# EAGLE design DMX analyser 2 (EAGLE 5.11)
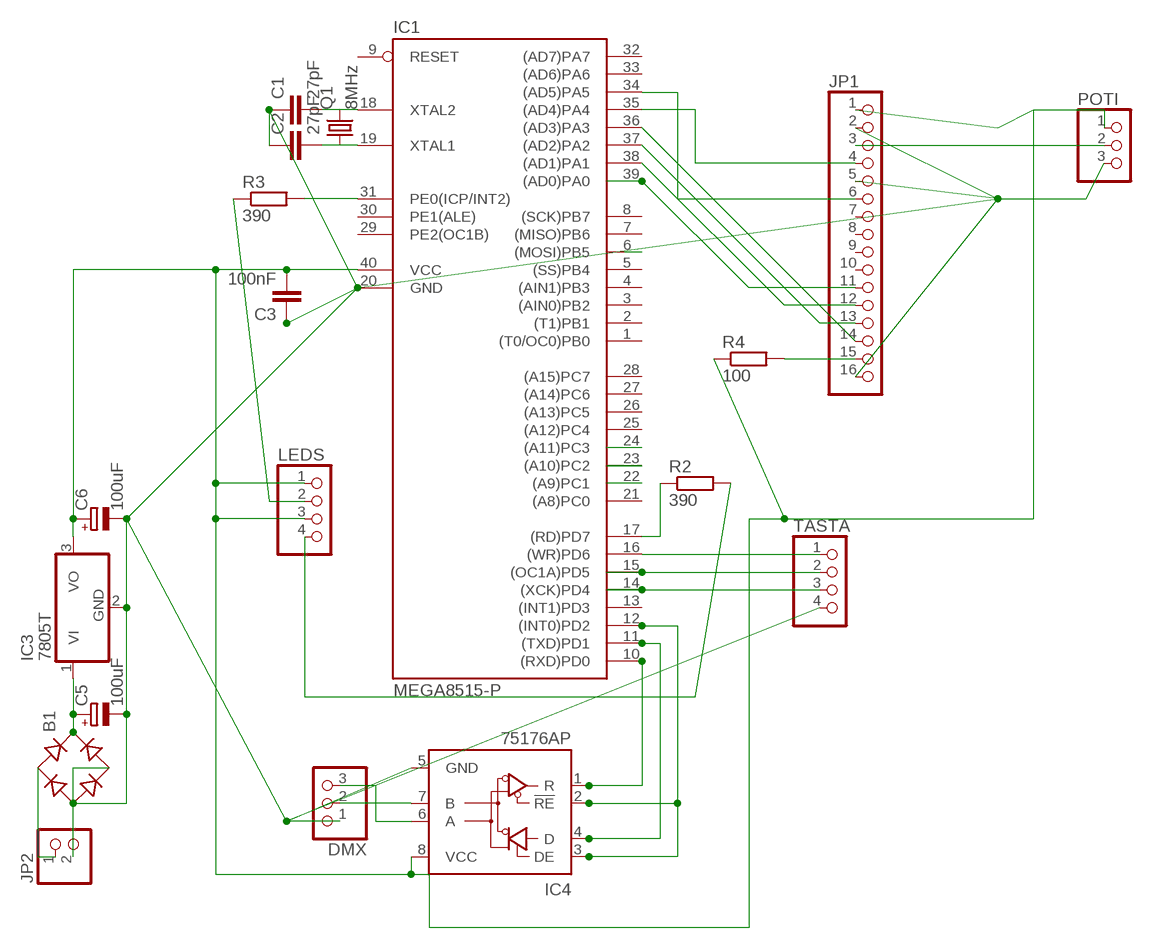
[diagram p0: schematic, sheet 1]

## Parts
B1  RB1A  [RB1A]
C1  27pF  C2,5-3  [C2.5-3]
C2  27pF  C2,5-3  [C2.5-3]
C3  100nF  C2.5/5  [C2.5-5]
C5  100uF  CPOL-EUE2.5-6  [E2,5-6]
C6  100uF  CPOL-EUE2.5-6  [E2,5-6]
DMX  PINHD-1X3/90  [1X03/90]
IC1  MEGA8515-P  [DIL40]
IC3  7805T  [TO220H]
IC4  75176AP  [DIL08]
JP1  PINHD-1X16  [1X16]
JP2  PINHD-1X2/90  [1X02/90]
LEDS  PINHD-1X4/90  [1X04/90]
POTI  PINHD-1X3/90  [1X03/90]
Q1  8MHz  CRYSTALHC49S  [HC49/S]
R2  390  R-EU_M1206  [M1206]
R3  390  R-EU_M1206  [M1206]
R4  100  R-EU_M1206  [M1206]
TASTA  PINHD-1X4/90  [1X04/90]

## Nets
N$1: C1.2 IC1.18(XTAL2) Q1.2
N$2: C2.2 IC1.19(XTAL1) Q1.1
N$3: DMX.2 IC4.7(B)
N$4: DMX.3 IC4.6(A)
N$5: IC1.6((MOSI)PB5)
N$6: JP1.3 POTI.2
N$7: IC1.10((RXD)PD0) IC4.1(R)
N$8: IC1.11((TXD)PD1) IC4.4(D)
N$9: IC1.16((WR)PD6) TASTA.1
N$10: C3.2 C6.+ IC1.40(VCC) IC3.3(VO) IC4.8(VCC) JP1.1 LEDS.1 LEDS.3 POTI.1 R4.1
N$11: LEDS.2 R3.1
N$12: LEDS.4 R2.2
N$13: IC1.31(PE0(ICP/INT2)) R3.2
N$14: IC1.35((AD4)PA4) JP1.4
N$15: B1.AC1 JP2.1
N$16: B1.+ C5.+ IC3.1(VI)
N$17: IC1.12((INT0)PD2) IC4.2(!RE) IC4.3(DE)
N$18: IC1.34((AD5)PA5) JP1.6
N$21: IC1.36((AD3)PA3) JP1.14
N$23: IC1.17((RD)PD7) R2.1
N$24: IC1.37((AD2)PA2) JP1.13
N$25: IC1.38((AD1)PA1) JP1.12
N$26: JP1.15 R4.2
N$27: B1.AC2 JP2.2
N$28: IC1.24((A11)PC3)
N$29: IC1.23((A10)PC2)
N$30: IC1.22((A9)PC1)
N$31: B1.- C1.1 C2.1 C3.1 C5.- C6.- DMX.1 IC1.20(GND) IC3.2(GND) IC4.5(GND) JP1.2 JP1.5 JP1.16 POTI.3 TASTA.4
N$37: IC1.39((AD0)PA0) JP1.11
N$64: IC1.15((OC1A)PD5) TASTA.2
N$65: IC1.14((XCK)PD4) TASTA.3
Unconnected: IC1.1((T0/OC0)PB0) IC1.2((T1)PB1) IC1.3((AIN0)PB2) IC1.4((AIN1)PB3) IC1.5((SS)PB4) IC1.7((MISO)PB6) IC1.8((SCK)PB7) IC1.9(RESET) IC1.13((INT1)PD3) IC1.21((A8)PC0) IC1.25((A12)PC4) IC1.26((A13)PC5) IC1.27((A14)PC6) IC1.28((A15)PC7) IC1.29(PE2(OC1B)) IC1.30(PE1(ALE)) IC1.32((AD7)PA7) IC1.33((AD6)PA6) JP1.7 JP1.8 JP1.9 JP1.10

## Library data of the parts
B1 = rectifier:RB1A: RECTIFIER 1 A
C1-C3 = capacitor-wima:C: CAPACITOR
C5 C6 = rcl:CPOL-EU: POLARIZED CAPACITOR, European symbol
DMX POTI = pinhead:PINHD-1X3: PIN HEADER
IC1 = atmel:MEGA8515-P: MICROCONTROLLER 8 Kbytes FLASH 512 bytes SRAM 512 bytes EEPROM USART 8-channel 10 bit ADC Source: avr.lbr; MPN: ATMEGA8515-16PU; OC_FARNELL: 9171401; OC_NEWARK: 01M6905
IC3 = linear:78*: Positive VOLTAGE REGULATOR Source: http://cache.national.com/ds/LM/LM78L05.pdf http://www.fairchildsemi.com/ds/LM/LM7805.pdf
IC4 = 751xx:75176A: DIFFERENTIAL BUS TRANSCEIVER Source: http://focus.ti.com/lit/ds/symlink/sn75176a.pdf
JP1 = pinhead:PINHD-1X16: PIN HEADER
JP2 = pinhead:PINHD-1X2: PIN HEADER
LEDS TASTA = pinhead:PINHD-1X4: PIN HEADER
Q1 = crystal:CRYSTAL: CRYSTAL; OC_FARNELL: 1667008; OC_NEWARK: unknown
R2-R4 = resistor:R-EU_: RESISTOR, European symbol

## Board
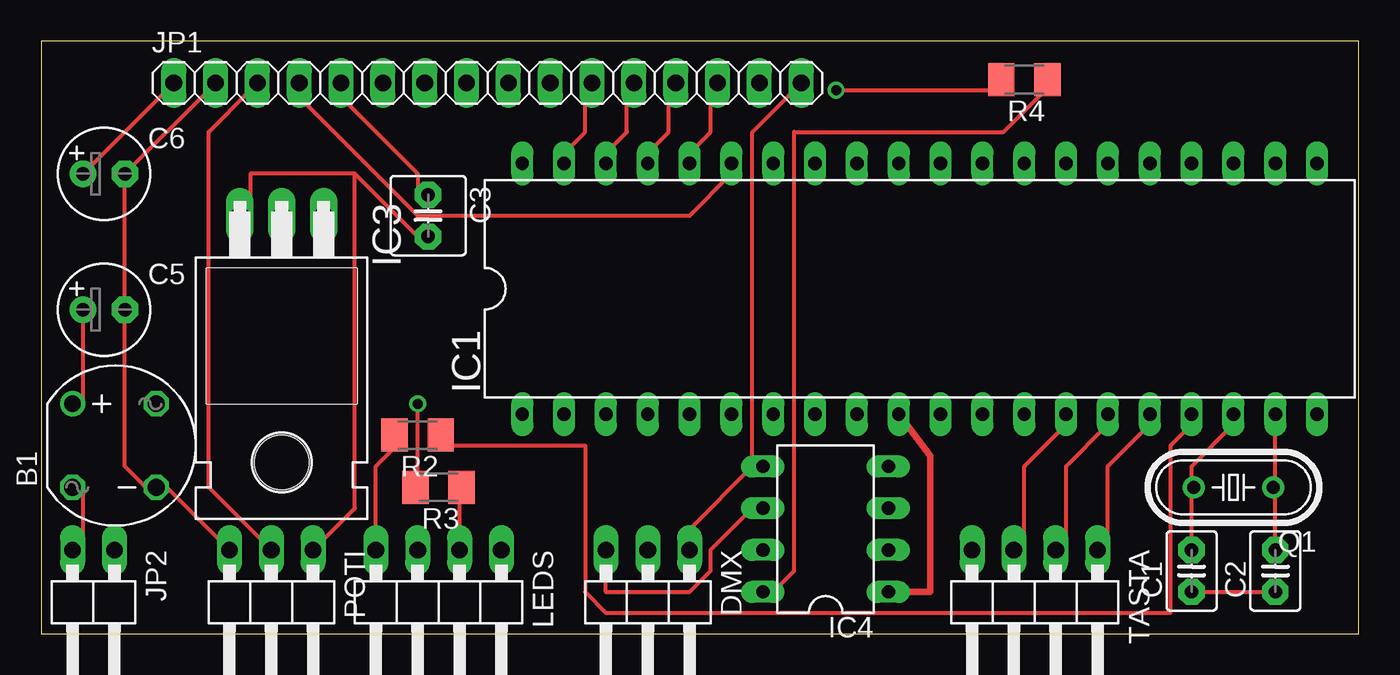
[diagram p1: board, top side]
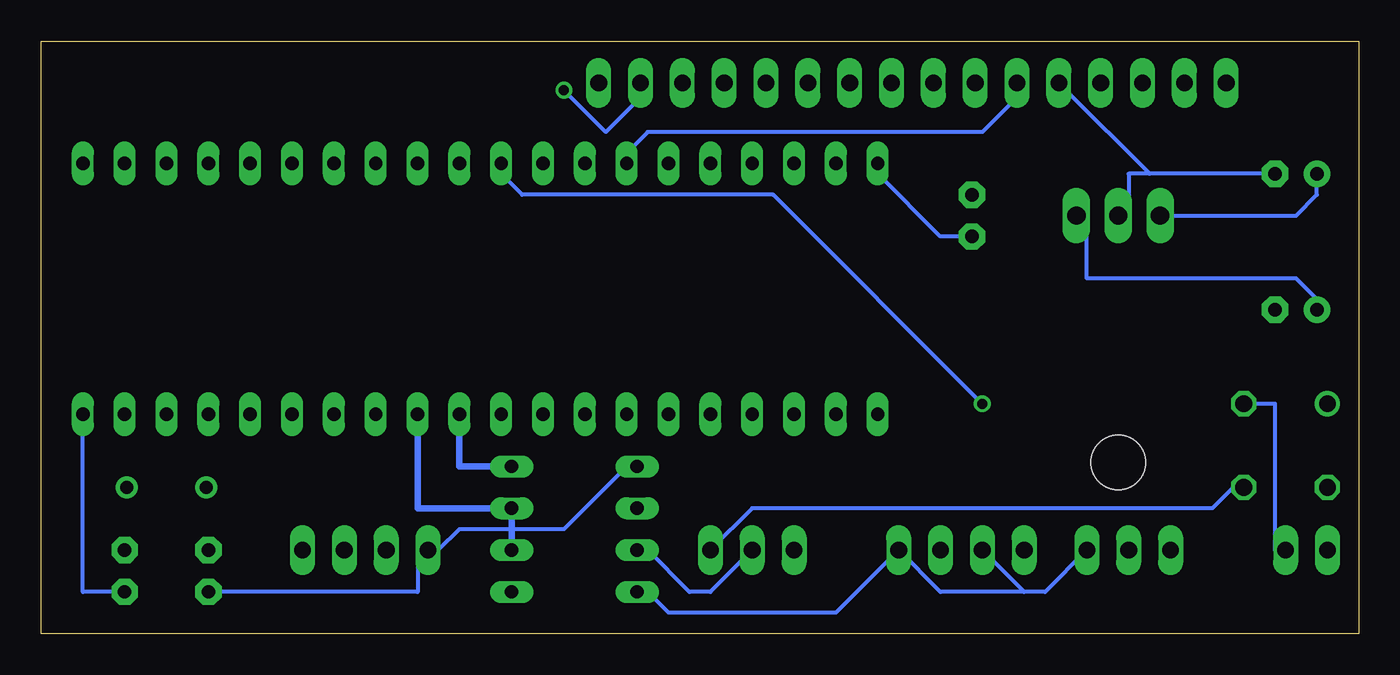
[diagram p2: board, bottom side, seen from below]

Size 80 x 36 mm. Coordinates in mm from the lower left corner, seen from the top.
Outline: 0,0 80,0 80,36 0,36 0,0
Copper layers (1*16): Top 0.035mm / dielectric 1.5mm / Bottom 0.035mm
Design rules "default": minimum track width 10mil, minimum drill 24mil, track to track 8mil, track to pad 8mil, pad to pad 8mil, via to via 8mil, smd to smd 8mil, copper to edge 40mil, drill to drill 8mil, minimum pad ring 10mil, minimum via ring 8mil, stop-mask expansion 4mil, vias tented up to drill 0mil, thermal gap 10mil

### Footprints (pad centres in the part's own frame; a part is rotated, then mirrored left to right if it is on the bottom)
RB1A = drill 1.016 round: + -2.54,2.54 | drill 1.016 octagon: - 2.54,-2.54; AC1 2.54,2.54; AC2 -2.54,-2.54
C2.5-3 = drill 0.813 pad 1.6 octagon: 1 -1.27,0; 2 1.27,0
C2.5-5 = drill 0.813 pad 1.6 octagon: 1 -1.27,0; 2 1.27,0
E2,5-6 = drill 0.813 pad 1.6 round: + -1.27,0 | drill 0.813 pad 1.6 octagon: - 1.27,0
1X03/90 = drill 1.016 long: 1 -2.54,-3.81; 2 0,-3.81; 3 2.54,-3.81
DIL40 = drill 0.813 long: 1 -24.13,-7.62; 2 -21.59,-7.62; 3 -19.05,-7.62; 4 -16.51,-7.62; 5 -13.97,-7.62; 6 -11.43,-7.62; 7 -8.89,-7.62; 8 -6.35,-7.62; 9 -3.81,-7.62; 10 -1.27,-7.62; 11 1.27,-7.62; 12 3.81,-7.62; 13 6.35,-7.62; 14 8.89,-7.62; 15 11.43,-7.62; 16 13.97,-7.62; 17 16.51,-7.62; 18 19.05,-7.62; 19 21.59,-7.62; 20 24.13,-7.62; 21 24.13,7.62; 22 21.59,7.62; 23 19.05,7.62; 24 16.51,7.62; 25 13.97,7.62; 26 11.43,7.62; 27 8.89,7.62; 28 6.35,7.62; 29 3.81,7.62; 30 1.27,7.62; 31 -1.27,7.62; 32 -3.81,7.62; 33 -6.35,7.62; 34 -8.89,7.62; 35 -11.43,7.62; 36 -13.97,7.62; 37 -16.51,7.62; 38 -19.05,7.62; 39 -21.59,7.62; 40 -24.13,7.62
TO220H = drill 1.118 long: 1 -2.54,-10.16; 2 0,-10.16; 3 2.54,-10.16 | hole 3.302: 0,4.826
DIL08 = drill 0.813 long: 1 -3.81,-3.81; 2 -1.27,-3.81; 3 1.27,-3.81; 4 3.81,-3.81; 5 3.81,3.81; 6 1.27,3.81; 7 -1.27,3.81; 8 -3.81,3.81
1X16 = drill 1.016 long: 1 -19.05,0; 2 -16.51,0; 3 -13.97,0; 4 -11.43,0; 5 -8.89,0; 6 -6.35,0; 7 -3.81,0; 8 -1.27,0; 9 1.27,0; 10 3.81,0; 11 6.35,0; 12 8.89,0; 13 11.43,0; 14 13.97,0; 15 16.51,0; 16 19.05,0
1X02/90 = drill 1.016 long: 1 -1.27,-3.81; 2 1.27,-3.81
1X04/90 = drill 1.016 long: 1 -3.81,-3.81; 2 -1.27,-3.81; 3 1.27,-3.81; 4 3.81,-3.81
HC49/S = drill 0.813 round: 1 -2.413,0; 2 2.413,0
M1206 = smd 1.6 x 2: 1 -1.4,0; 2 1.4,0

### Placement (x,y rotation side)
B1  4.45,11.43 0 top
C1  69.85,3.81 90 top
C2  74.93,3.81 90 top
C3  23.5,25.4 270 top
C5  3.81,19.68 0 top
C6  3.81,27.94 0 top
DMX  36.83,1.27 180 top
IC1  53.34,20.95 0 top
IC3  14.61,15.24 180 top
IC4  47.62,6.35 90 top
JP1  27.1,33.46 0 top
JP2  3.17,1.27 180 top
LEDS  24.13,1.27 180 top
POTI  13.97,1.27 180 top
Q1  72.39,8.89 180 top
R2  22.86,12.06 180 top
R3  24.13,8.89 180 top
R4  59.69,33.66 180 top
TASTA  60.33,1.27 180 top

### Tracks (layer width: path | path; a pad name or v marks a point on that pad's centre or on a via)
N$1
  Top 0.254: C1.2 69.85,8.89 | 69.85,8.89 69.85,10.16 72.39,12.7 IC1.18 | 69.85,8.89 Q1.2
N$2
  Top 0.254: 74.93,8.89 IC1.19 | C2.2 74.93,8.89 | 74.93,8.89 Q1.1
N$3
  Bottom 0.254: DMX.2 39.37,2.54 40.64,2.54 43.18,5.08 IC4.7
N$4
  Top 0.254: DMX.3 34.29,2.54 39.37,2.54 40.64,3.81 40.64,5.08 43.18,7.62 IC4.6
N$6
  Top 0.254: POTI.2 10.16,8.89 10.16,30.48 12.7,33.02 JP1.3
N$7
  Top 0.406: IC4.1 53.98,2.54 53.98,10.79 IC1.10
N$8
  Bottom 0.406: IC4.4 54.61,10.16 IC1.11
N$9
  Top 0.254: IC1.16 67.31,12.7 64.77,10.16 64.77,5.08 TASTA.1
N$10
  Top 0.254: R4.1 60.96,33.02 58.42,30.48 45.72,30.48 45.72,3.81 44.45,2.54 IC4.8 | C6.+ 7.62,33.02 JP1.1 | 19.05,27.94 22.86,24.13 C3.2 | 19.05,27.94 12.7,27.94 12.7,25.4 IC3.3 | POTI.1 19.05,7.62 19.05,27.94
  Bottom 0.254: POTI.1 19.05,2.54 20.32,2.54 | 20.32,2.54 LEDS.3 | 20.32,2.54 25.4,2.54 LEDS.1 31.75,1.27 41.91,1.27 43.18,2.54 IC4.8 | IC1.40 29.21,27.94 25.4,24.13 C3.2 | IC3.3 3.81,25.4 2.54,26.67 C6.+
N$11
  Top 0.254: LEDS.2 25.4,8.89 R3.1
N$12
  Top 0.254: LEDS.4 20.32,10.16 21.59,11.43 R2.2
N$13  (via drill 0.61)
  Top 0.254: v22.86,13.97 22.86,8.89 R3.2
  Bottom 0.254: v22.86,13.97 35.56,26.67 50.8,26.67 52.07,27.94 IC1.31
N$14
  Top 0.254: IC1.35 41.91,27.94 39.37,25.4 22.86,25.4 15.24,33.02 JP1.4
N$15
  Bottom 0.254: JP2.1 5.08,5.08 5.08,13.97 B1.AC1
N$16
  Top 0.254: B1.+ 2.54,13.97 C5.+
  Bottom 0.254: IC3.1 16.51,25.4 16.51,21.59 3.81,21.59 2.54,20.32 C5.+
N$17
  Bottom 0.406: IC4.2 IC4.3 57.15,7.62 IC1.12
N$18
  Bottom 0.254: IC1.34 44.45,29.21 43.18,30.48 22.86,30.48 20.32,33.02 JP1.6
N$21
  Top 0.254: IC1.36 39.37,29.21 40.64,30.48 40.64,33.02 JP1.14
N$23
  Top 0.254: R2.1 24.13,11.43 33.02,11.43 33.02,2.54 34.29,1.27 68.58,1.27 68.58,11.43 69.85,12.7 IC1.17
N$24
  Top 0.254: IC1.37 36.83,29.21 38.1,30.48 38.1,33.02 JP1.13
N$25
  Top 0.254: IC1.38 34.29,29.21 35.56,30.48 35.56,33.02 JP1.12
N$26  (via drill 0.61)
  Top 0.254: v48.26,33.02 58.42,33.02 R4.2
  Bottom 0.254: v48.26,33.02 45.72,30.48 43.18,33.02 JP1.15
N$27
  Top 0.254: JP2.2 2.54,5.08 2.54,8.89 B1.AC2
N$31
  Top 0.254: JP1.5 17.78,33.02 22.86,27.94 22.86,26.67 C3.1 | POTI.3 7.62,8.89 B1.- 6.35,8.89 5.08,10.16 C5.- C6.- 10.16,33.02 JP1.2 | C1.1 C2.1 | 43.18,10.16 39.37,6.35 DMX.1 | 43.18,10.16 43.18,30.48 45.72,33.02 JP1.16 | 43.18,10.16 IC4.5
  Bottom 0.254: C6.- 12.7,27.94 | 12.7,27.94 13.97,27.94 13.97,25.4 IC3.2 | 12.7,27.94 17.78,33.02 JP1.5 | C2.1 77.47,2.54 IC1.20 | C1.1 57.15,2.54 57.15,5.08 TASTA.4 55.88,5.08 54.61,6.35 48.26,6.35 44.45,10.16 IC4.5 | DMX.1 36.83,7.62 8.89,7.62 7.62,8.89 B1.-
N$37
  Top 0.254: IC1.39 31.75,29.21 33.02,30.48 33.02,33.02 JP1.11
N$64
  Top 0.254: IC1.15 64.77,12.7 62.23,10.16 62.23,5.08 TASTA.2
N$65
  Top 0.254: IC1.14 62.23,12.7 59.69,10.16 59.69,5.08 TASTA.3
